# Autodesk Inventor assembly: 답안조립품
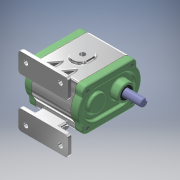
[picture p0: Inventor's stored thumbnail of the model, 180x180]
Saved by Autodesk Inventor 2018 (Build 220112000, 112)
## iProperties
Created: 2023-06
Part Number: 답안조립품
Material: 일반
Document SubType Name: Assembly
Designer: home
Author: home
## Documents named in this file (12)
- C:\Users\home\Desktop\730606V1014\답안조립품.iam
- C:\Users\home\Desktop\730606V1014\본체.ipt
- C:\Users\home\Desktop\730606V1014\뒷커버.ipt
- C:\Users\home\Desktop\730606V1014\가스켓.ipt
- C:\Users\home\Desktop\730606V1014\앞커버.ipt
- C:\Users\home\Desktop\730606V1014\오일실 15 25 7.ipt
- C:\Users\home\Desktop\730606V1014\니들베어링 NA 4902.ipt
- C:\Users\home\Desktop\730606V1014\서브 드라이브 기어.ipt
- C:\Users\home\Desktop\730606V1014\메인 드라이브 기어.ipt
- C:\Users\home\Desktop\730606V1014\샤프트.ipt
- C:\Users\home\Desktop\730606V1014\묻힘키 6x6x40.ipt
- C:\Users\home\Desktop\730606V1014\육각 소켓 머리 볼트 M8 x 100.ipt
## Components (2 placed, 1 different names)
1. 가스켓:1
2. 가스켓:2
